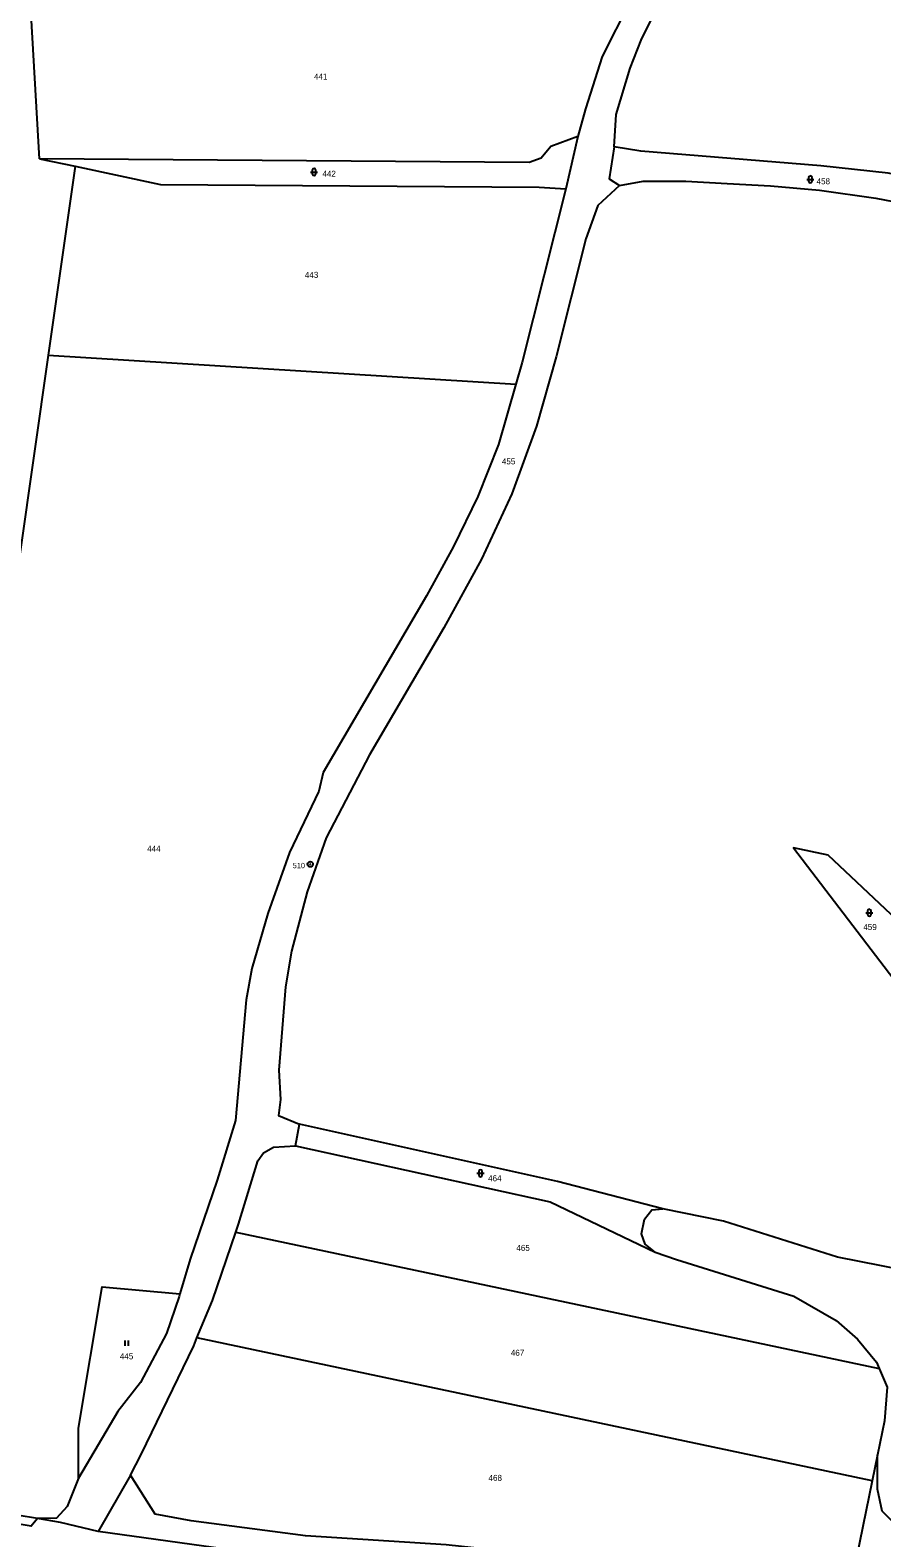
# Model space of a CAD drawing. Extents: x -769392 to -767038, y -1018329 to -1015269.
# Drawn here: x -768267.7 to -768027, y -1016192.3 to -1015766.2 of the extents above; entities that cross this region are included whole.
import ezdxf
from ezdxf.enums import TextEntityAlignment as Align

# ---------------------------------------------------------------- set-up
doc = ezdxf.new("R2010")
doc.units = 0
doc.header["$LTSCALE"] = 0.68
for name, color, linetype, lineweight in [('1', 7, 'Continuous', 25), ('3', 7, 'Continuous', 25), ('8', 7, 'Continuous', 25)]:
    doc.layers.add(name, color=color, linetype=linetype, lineweight=lineweight)
doc.layers.add('2', color=7, linetype='Continuous')

msp = doc.modelspace()

# ---------------------------------------------------------------- linework, layer by layer
at = {"layer": '1'}
for p, q in [((-768265.13, -1015802.54), (-768267.7, -1015756.93)), ((-768112.9, -1015796.24), (-768116.36, -1015811.01)), ((-768265.13, -1015802.54), (-768255.02, -1015804.69)), ((-768255.02, -1015804.69), (-768262.64, -1015858.01)), ((-768262.64, -1015858.01), (-768130.47, -1015866.28)), ((-768192.71, -1016081.53), (-768191.64, -1016075.4)), ((-768209.64, -1016105.89), (-768027.74, -1016144.42)), ((-768029.76, -1016176.15), (-768220.58, -1016135.73)), ((-768028.24, -1016168.79), (-768029.76, -1016176.15)), ((-768239.34, -1016174.56), (-768248.53, -1016190.48)), ((-768029.76, -1016176.15), (-768037.13, -1016211.88))]:
    msp.add_line(p, q, dxfattribs=at)
for points in [[(-768102.72, -1015799.16), (-768102.1, -1015790.03), (-768098.18, -1015776.92), (-768095.07, -1015769.01), (-768068.74, -1015715.9), (-768057.97, -1015694.98), (-768044.47, -1015662.72), (-768037.18, -1015638.56), (-768032.78, -1015630.79)], [(-768098.24, -1015758.2), (-768106.1, -1015773.64), (-768110.79, -1015788.45), (-768112.9, -1015796.24)], [(-768112.9, -1015796.24), (-768120.56, -1015799.12), (-768123.3, -1015802.42), (-768126.7, -1015803.59), (-768265.13, -1015802.54)], [(-768102.72, -1015799.16), (-768104.08, -1015808.2), (-768101.13, -1015810.13)], [(-768101.13, -1015810.13), (-768094.51, -1015808.91), (-768082.41, -1015808.9), (-768070.71, -1015809.58), (-768058.51, -1015810.25), (-768044.63, -1015811.45), (-768028.69, -1015813.71), (-768006.21, -1015818.03), (-767993.85, -1015819.67), (-767983.23, -1015821.18), (-767976.61, -1015821.7), (-767972.44, -1015821.41), (-767990.87, -1015814.83), (-768008.11, -1015810.14), (-768025.22, -1015806.6), (-768044.3, -1015804.53), (-768095.11, -1015800.38), (-768102.72, -1015799.16)], [(-768255.02, -1015804.69), (-768230.89, -1015809.8), (-768123.87, -1015810.61), (-768116.36, -1015811.01)], [(-768101.13, -1015810.13), (-768107.3, -1015815.76), (-768110.67, -1015825.23), (-768119.07, -1015858.49), (-768124.67, -1015878.1), (-768131.63, -1015897.21), (-768140.18, -1015915.73), (-768150.82, -1015935.08), (-768171.79, -1015970.99), (-768184.03, -1015994.47), (-768189.41, -1016009.75), (-768193.86, -1016026.47), (-768195.57, -1016036.59), (-768197.46, -1016060.12), (-768196.94, -1016068.38), (-768197.52, -1016072.93), (-768191.64, -1016075.4)], [(-768116.36, -1015811.01), (-768128.69, -1015860.04), (-768130.47, -1015866.28)], [(-768262.64, -1015858.01), (-768282.68, -1015998.29), (-768308.65, -1016180.07)], [(-768130.47, -1015866.28), (-768135.33, -1015883.28), (-768141.21, -1015897.97), (-768148.05, -1015912.14), (-768155.72, -1015926.07), (-768184.89, -1015976.03), (-768186.15, -1015981.24), (-768194.39, -1015998.57), (-768200.57, -1016015.86), (-768205.07, -1016031.35), (-768206.7, -1016040.21), (-768209.74, -1016074.29), (-768214.86, -1016091.22), (-768222.48, -1016113.55), (-768225.41, -1016123.3)], [(-768006.53, -1016032.9), (-768042.22, -1015999.38), (-768052, -1015997.24), (-768017.2, -1016042.76)], [(-768088.91, -1016099.25), (-768118.72, -1016091.53), (-768191.64, -1016075.4)], [(-768209.64, -1016105.89), (-768208.87, -1016103.65), (-768203.34, -1016085.73), (-768201.83, -1016083.44), (-768198.99, -1016081.9), (-768192.71, -1016081.53)], [(-768192.71, -1016081.53), (-768120.76, -1016097.28), (-768091.07, -1016111.54)], [(-768091.07, -1016111.54), (-768093.91, -1016109.26), (-768094.96, -1016106.39), (-768094.1, -1016102.19), (-768092.03, -1016099.57), (-768088.91, -1016099.25)], [(-767896.62, -1016240.82), (-767912.56, -1016234.13), (-767920.31, -1016228.66), (-767925.99, -1016221.98), (-767933.3, -1016211.56), (-767939.27, -1016201.17), (-767942.28, -1016192.67), (-767942.7, -1016184.35), (-767943.08, -1016182.35), (-767947.41, -1016178.51), (-767951.73, -1016175.96), (-767976.13, -1016166.75), (-767982.69, -1016161.31), (-767988.39, -1016150.96), (-767989.96, -1016141.37), (-767991.47, -1016134.18), (-767994.3, -1016128.17), (-768001.87, -1016121.89), (-768005.47, -1016120.25), (-768014.65, -1016117.84), (-768027.12, -1016115.35), (-768039.52, -1016112.92), (-768071.74, -1016102.81), (-768088.91, -1016099.25)], [(-768220.58, -1016135.73), (-768216.19, -1016125.17), (-768209.64, -1016105.89)], [(-768091.07, -1016111.54), (-768085.01, -1016113.57), (-768051.92, -1016123.94), (-768039.91, -1016130.87), (-768033.92, -1016136.07), (-768028.53, -1016142.59), (-768027.74, -1016144.42)], [(-768254.03, -1016175.4), (-768254.11, -1016161.31), (-768247.42, -1016121.37), (-768225.41, -1016123.3)], [(-768225.41, -1016123.3), (-768225.65, -1016124.09), (-768229.21, -1016134.47), (-768236.51, -1016148.39), (-768242.97, -1016156.59), (-768254.03, -1016175.4)], [(-768239.34, -1016174.56), (-768236.4, -1016168.72), (-768221.51, -1016137.97), (-768220.58, -1016135.73)], [(-768027.74, -1016144.42), (-768025.47, -1016149.67), (-768026.26, -1016159.19), (-768028.24, -1016168.79)], [(-768265.65, -1016186.8), (-768267.45, -1016188.93), (-768339.18, -1016177.1), (-768385.9, -1016172.79), (-768466.41, -1016162.88), (-768516.66, -1016155.93)], [(-767911.07, -1016254.35), (-767911.35, -1016254.24), (-767913.83, -1016253.23), (-767922.4, -1016249.43), (-767929.72, -1016245.52), (-767936.18, -1016240.92), (-767940.03, -1016237.62), (-767944.46, -1016232.99), (-767951.01, -1016226.59), (-767958.59, -1016221.19), (-767971.23, -1016214.07), (-767985.88, -1016207.38), (-767992.63, -1016204.28), (-768002.1, -1016199.96), (-768015.26, -1016193.2), (-768022.33, -1016189.3), (-768026.9, -1016184.75), (-768028.26, -1016178.48), (-768028.24, -1016168.79)], [(-768254.03, -1016175.4), (-768257.28, -1016183.39), (-768260.31, -1016186.66), (-768265.65, -1016186.8)], [(-768037.13, -1016211.88), (-768047.42, -1016209.86), (-768054.8, -1016209.07), (-768071.38, -1016207.24), (-768107.44, -1016201.58), (-768130.2, -1016196.4), (-768150.13, -1016194.23), (-768189.94, -1016191.66), (-768222.23, -1016187.48), (-768232.37, -1016185.6), (-768239.34, -1016174.56)], [(-768265.65, -1016186.8), (-768300.2, -1016181.16), (-768308.65, -1016180.07)], [(-768248.53, -1016190.48), (-768259.14, -1016187.96), (-768265.65, -1016186.8)], [(-768042.9, -1016221.04), (-768063.84, -1016215.78), (-768093.2, -1016215.76), (-768123.63, -1016207.43), (-768162.24, -1016203.59), (-768189.43, -1016198.7), (-768248.53, -1016190.48)]]:
    msp.add_lwpolyline(points, dxfattribs=at)
at = {"layer": '3'}
for p, q in [((-768188.501, -1015806.301), (-768186.499, -1015806.301)), ((-768188.001, -1015805.801), (-768188.001, -1015806.802)), ((-768186.999, -1015806.802), (-768186.999, -1015805.801)), ((-768048.251, -1015808.391), (-768046.249, -1015808.391)), ((-768047.751, -1015807.891), (-768047.751, -1015808.892)), ((-768046.749, -1015808.892), (-768046.749, -1015807.891)), ((-768031.551, -1016015.611), (-768029.549, -1016015.611)), ((-768031.051, -1016015.111), (-768031.051, -1016016.112)), ((-768030.049, -1016016.112), (-768030.049, -1016015.111)), ((-768141.461, -1016089.221), (-768139.459, -1016089.221)), ((-768140.961, -1016088.721), (-768140.961, -1016089.722)), ((-768139.959, -1016089.722), (-768139.959, -1016088.721)), ((-768240.911, -1016137.99), (-768240.911, -1016136.49)), ((-768239.91, -1016137.99), (-768239.91, -1016136.49))]:
    msp.add_line(p, q, dxfattribs=at)
for centre, start, end in [((-768187.5, -1015805.8009), 0, 180), ((-768187.5, -1015806.8009), 180, 359.98789), ((-768047.25, -1015807.8909), 0, 180), ((-768047.25, -1015808.8909), 180, 359.98789), ((-768030.55, -1016015.1109), 0, 180), ((-768030.55, -1016016.1109), 180, 359.98789), ((-768140.46, -1016088.7209), 0, 180), ((-768140.46, -1016089.7209), 180, 359.98789)]:
    msp.add_arc(centre, 0.5, start, end, dxfattribs=at)
at = {"layer": '8'}
for radius in [0.75, 0.03]:
    msp.add_circle((-768188.57, -1016001.9098), radius, dxfattribs=at)

# ---------------------------------------------------------------- texts
at = {"layer": '2'}
for s, p in [('441', (-768187.5, -1015780.165)), ('442', (-768185.13, -1015807.645)), ('458', (-768045.46, -1015809.765)), ('443', (-768190.09, -1015836.215)), ('455', (-768134.4, -1015888.915)), ('444', (-768234.68, -1015998.395)), ('459', (-768032.25, -1016020.515)), ('464', (-768138.3, -1016091.505)), ('465', (-768130.31, -1016111.165)), ('467', (-768131.88, -1016140.815)), ('445', (-768242.39, -1016141.795)), ('468', (-768138.18, -1016176.165))]:
    msp.add_text(s, height=1.7, dxfattribs=at).set_placement(p)
at = {"layer": '8'}
msp.add_text('510', height=1.5, dxfattribs=at).set_placement((-768190.069, -1016003.027), align=Align.RIGHT)

doc.saveas('drawing.dxf')
